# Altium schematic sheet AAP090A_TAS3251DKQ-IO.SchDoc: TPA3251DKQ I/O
size 538 x 342 mm; Date: Not shown in title block; ApprovedBy: Not shown in title block; CheckedBy: Not shown in title block; Author: Not shown in title block; CompanyName: Not shown in title block; DrawnBy: LDN; Engineer: Not shown in title block; Organization: Not shown in title block; Address1: Not shown in title block; Address2: Not shown in title block; Address3: Not shown in title block; Address4: Not shown in title block; DocumentNumber: 4; Revision: Use project parameter SCH_Rev; SheetNumber: 4; SheetTotal: 6; PageSetup: Record=PageOptions¦CenterHorizontal=True¦CenterVertical=True¦PrintScale=1.00¦XCorrection=1.00¦YCorrection=1.00¦PrintKind=0¦BorderSize=5000000¦LeftOffset=0¦BottomOffset=0¦Orientation=2¦PaperLength=1000¦PaperWidth=1000¦Scale=100¦PaperSource=15¦PrintQuality=600¦MediaType=1¦DitherType=10¦PaperKind=Letter¦PrintScaleMode=1
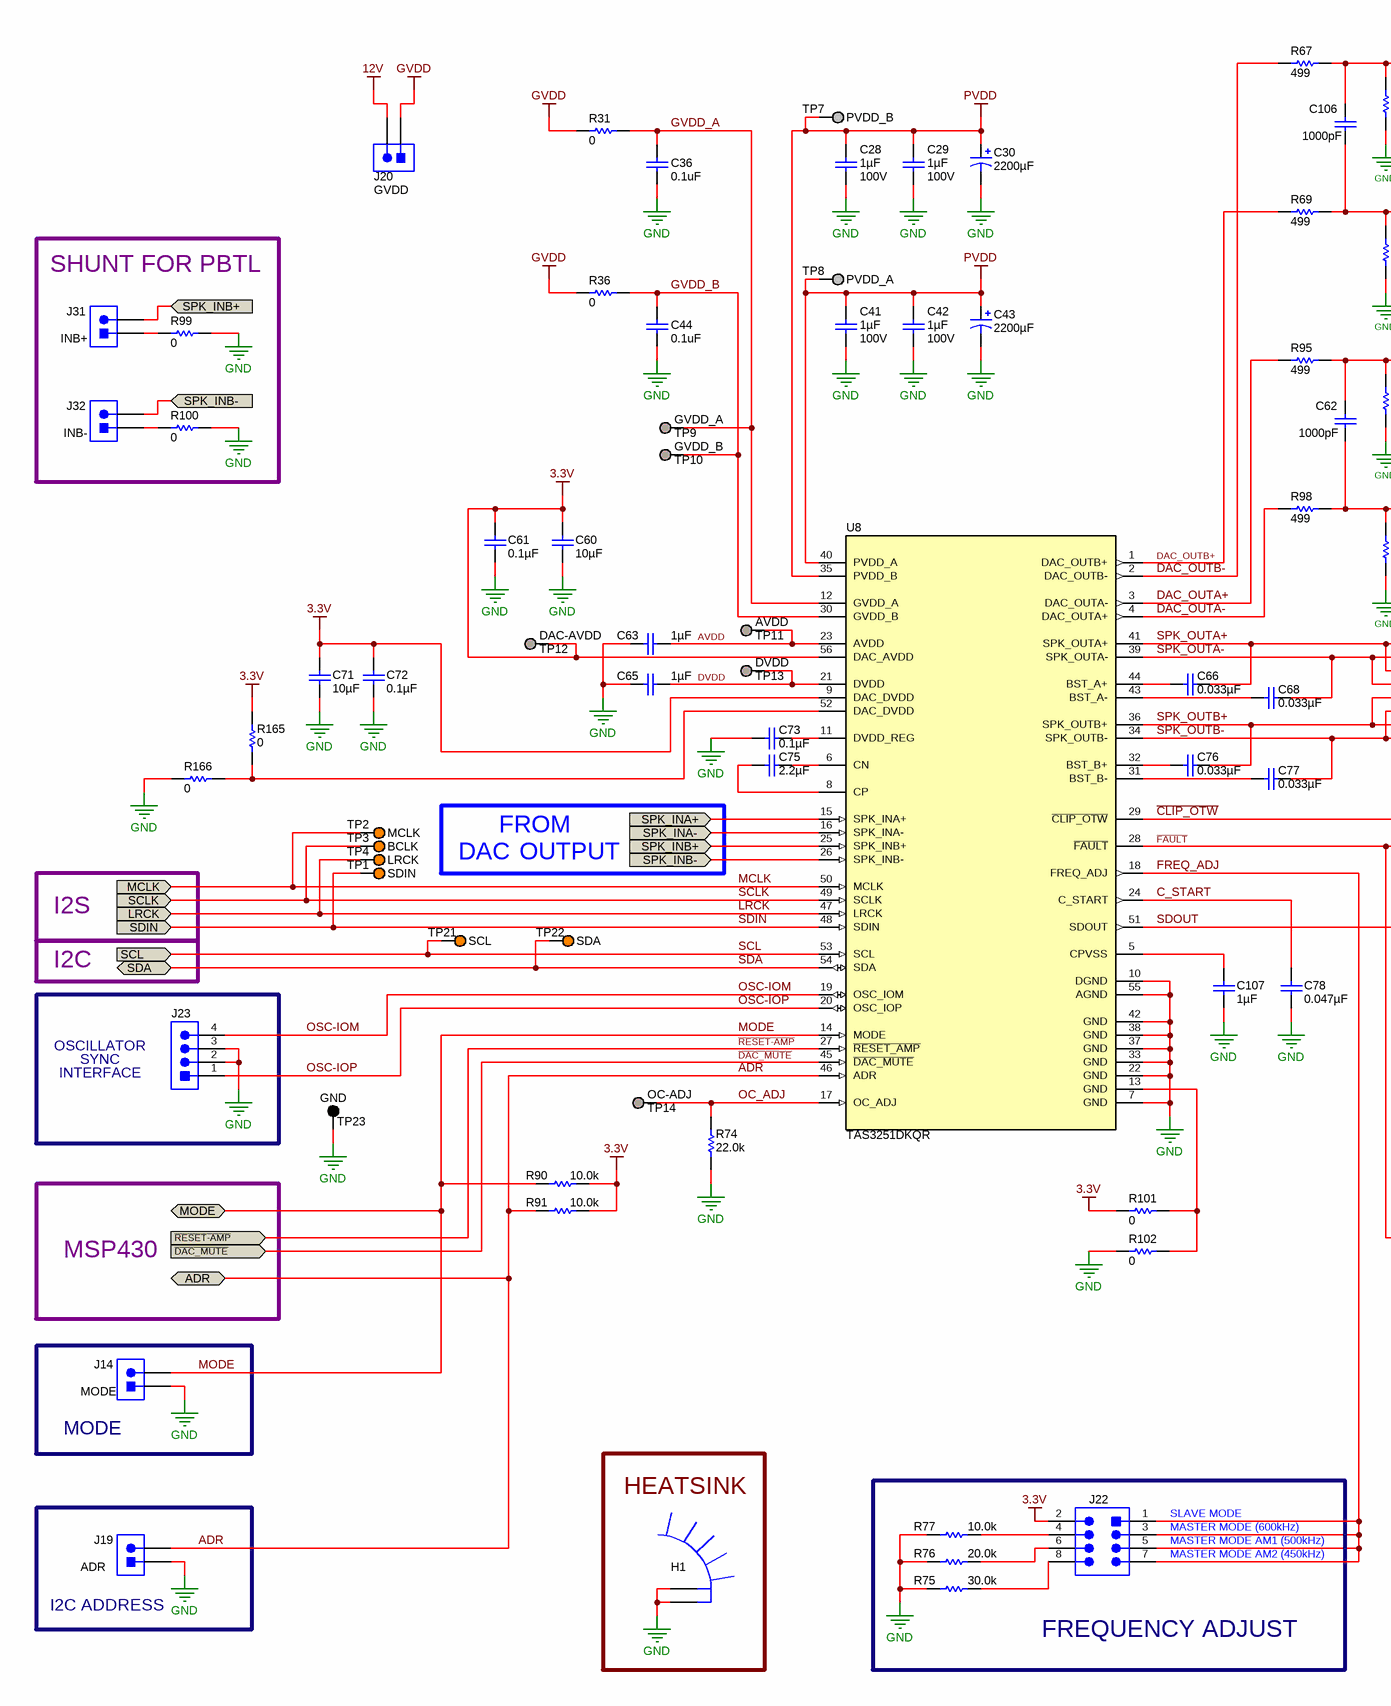
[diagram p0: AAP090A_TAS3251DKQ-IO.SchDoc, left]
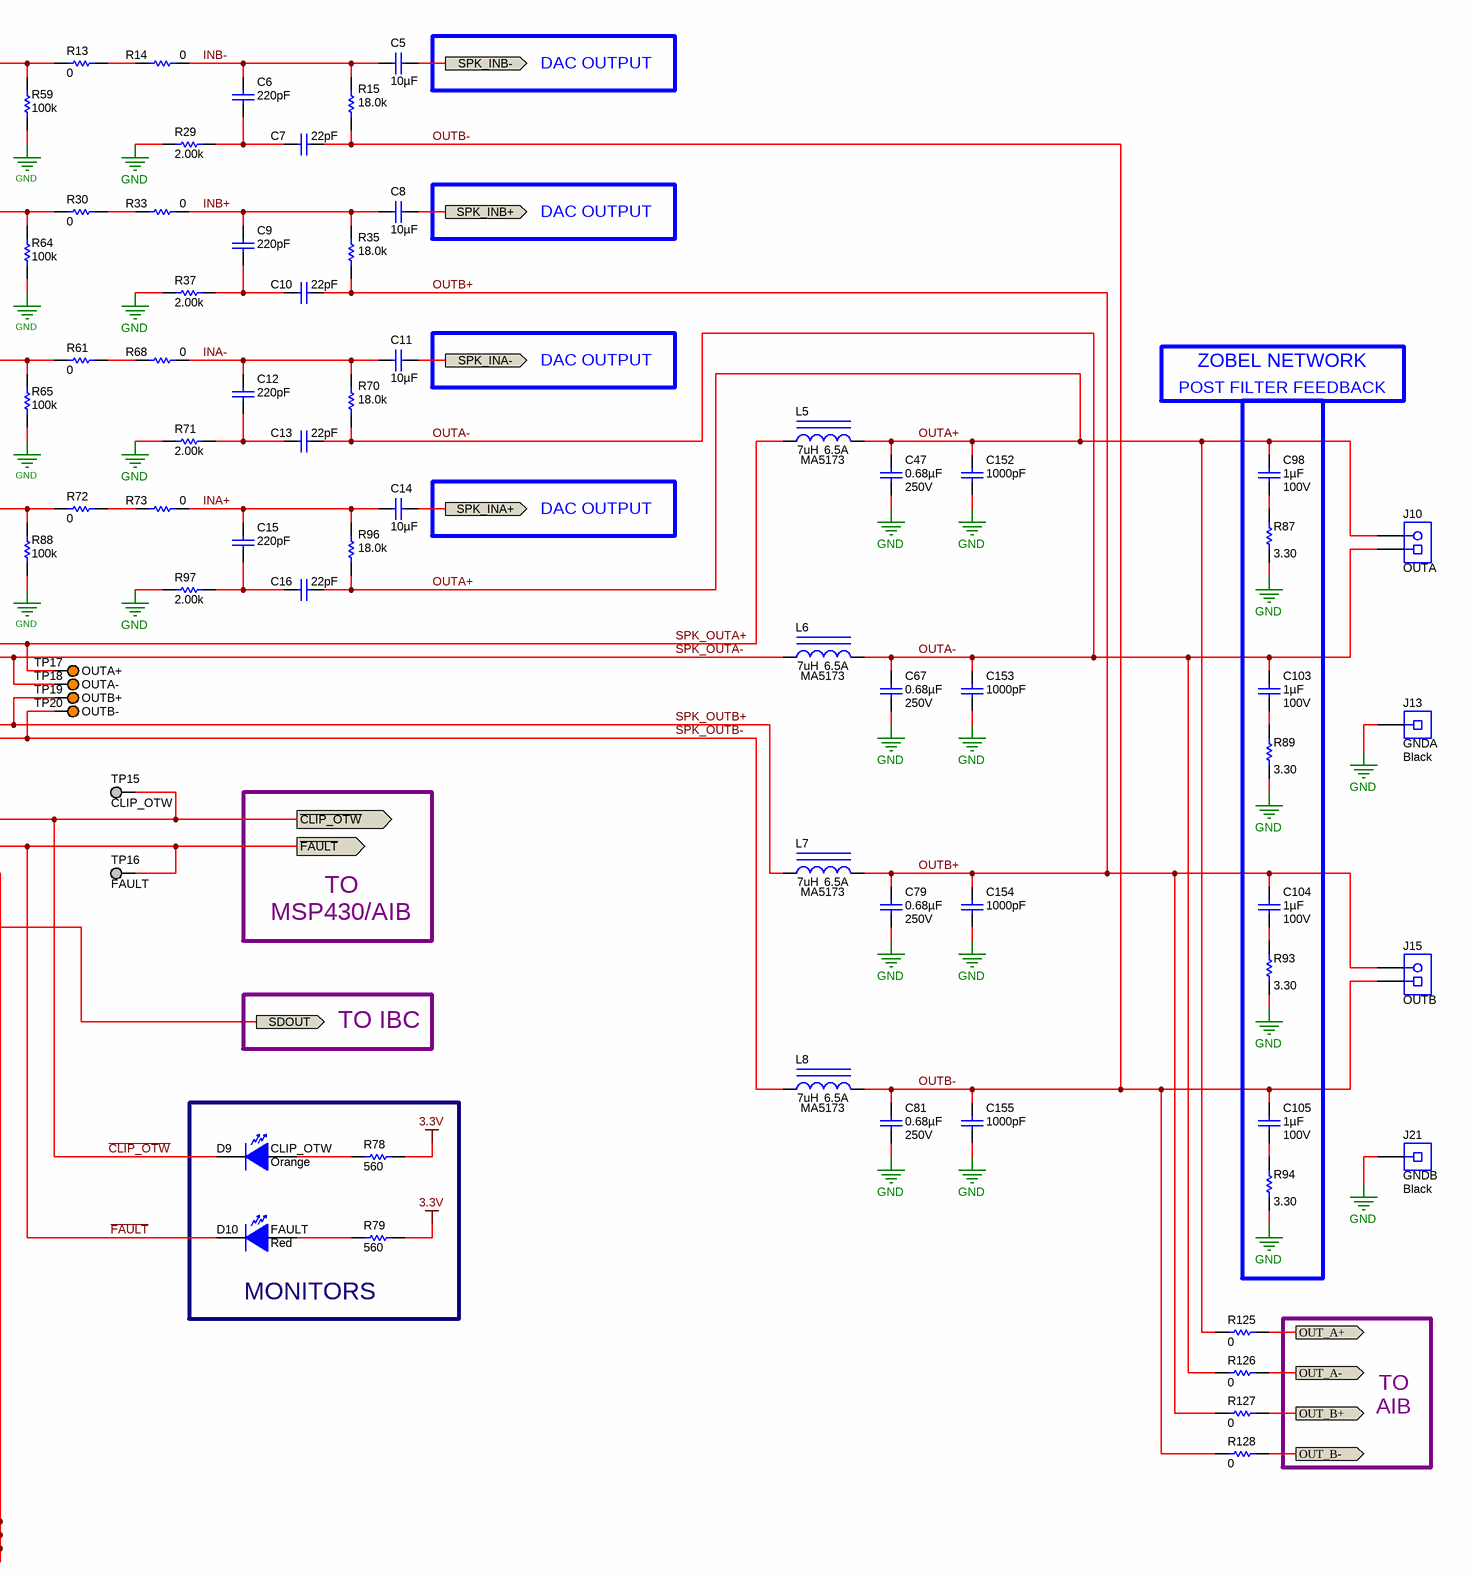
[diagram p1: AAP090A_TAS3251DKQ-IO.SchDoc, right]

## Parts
C5  ValueDisplayed: 10µF  [1206_180L]  (hidden comment: GRM31CR71C106KAC7L)
C6  ValueDisplayed: 220pF  [0603L]  (hidden comment: DNP)
C7  ValueDisplayed: 22pF  [0603L]  (hidden comment: DNP)
C8  ValueDisplayed: 10µF  [1206_180L]  (hidden comment: GRM31CR71C106KAC7L)
C9  ValueDisplayed: 220pF  [0603L]  (hidden comment: DNP)
C10  ValueDisplayed: 22pF  [0603L]  (hidden comment: DNP)
C11  ValueDisplayed: 10µF  [1206_180L]  (hidden comment: GRM31CR71C106KAC7L)
C12  ValueDisplayed: 220pF  [0603L]  (hidden comment: DNP)
C13  ValueDisplayed: 22pF  [0603L]  (hidden comment: DNP)
C14  ValueDisplayed: 10µF  [1206_180L]  (hidden comment: GRM31CR71C106KAC7L)
C15  ValueDisplayed: 220pF  [0603L]  (hidden comment: DNP)
C16  ValueDisplayed: 22pF  [0603L]  (hidden comment: DNP)
C28  ValueDisplayed: 1µF  Value2: 100V  [1206_180L]  (hidden comment: GRM31CR72A105KA01L)
C29  ValueDisplayed: 1µF  Value2: 100V  [1206_180L]  (hidden comment: GRM31CR72A105KA01L)
C30  ValueDisplayed: 2200µF  [FC_1800x3550]  (hidden comment: +)
C36  value 0.1uF  [0603L]  (hidden comment: C0603C104K5RACTU)
C41  ValueDisplayed: 1µF  Value2: 100V  [1206_180L]  (hidden comment: GRM31CR72A105KA01L)
C42  ValueDisplayed: 1µF  Value2: 100V  [1206_180L]  (hidden comment: GRM31CR72A105KA01L)
C43  ValueDisplayed: 2200µF  [FC_1800x3550]  (hidden comment: +)
C44  value 0.1uF  [0603L]  (hidden comment: C0603C104K5RACTU)
C47  ValueDisplayed: 0.68µF  Value2: 250V  [B32652_1800x900x1750]  (hidden comment: B32652A3684J)
C60  ValueDisplayed: 10µF  [0603L]  (hidden comment: GRM188R61A106ME69D)
C61  ValueDisplayed: 0.1µF  [0402L]  (hidden comment: GRM155R71A104KA01D)
C62  ValueDisplayed: 1000pF  [0402L]  (hidden comment: GRM1555C1H102JA01D)
C63  ValueDisplayed: 1µF  [0603L]  (hidden comment: GRM188R71C105KA12D)
C65  ValueDisplayed: 1µF  [0603L]  (hidden comment: GRM188R71C105KA12D)
C66  ValueDisplayed: 0.033µF  [0603L]  (hidden comment: GRM188R71E333KA01D)
C67  ValueDisplayed: 0.68µF  Value2: 250V  [B32652_1800x900x1750]  (hidden comment: B32652A3684J)
C68  ValueDisplayed: 0.033µF  [0603L]  (hidden comment: GRM188R71E333KA01D)
C71  ValueDisplayed: 10µF  [0603L]  (hidden comment: GRM188R61A106ME69D)
C72  ValueDisplayed: 0.1µF  [0402L]  (hidden comment: GRM155R71A104KA01D)
C73  ValueDisplayed: 0.1µF  [0402L]  (hidden comment: GRM155R71A104KA01D)
C75  ValueDisplayed: 2.2µF  [0402L]  (hidden comment: C1005X5R1A225K050BC)
C76  ValueDisplayed: 0.033µF  [0603L]  (hidden comment: GRM188R71E333KA01D)
C77  ValueDisplayed: 0.033µF  [0603L]  (hidden comment: GRM188R71E333KA01D)
C78  ValueDisplayed: 0.047µF  [0603L]  (hidden comment: GRM188R71H473KA61D)
C79  ValueDisplayed: 0.68µF  Value2: 250V  [B32652_1800x900x1750]  (hidden comment: B32652A3684J)
C81  ValueDisplayed: 0.68µF  Value2: 250V  [B32652_1800x900x1750]  (hidden comment: B32652A3684J)
C98  ValueDisplayed: 1µF  Value2: 100V  [1206_180L]  (hidden comment: DNP)
C103  ValueDisplayed: 1µF  Value2: 100V  [1206_180L]  (hidden comment: DNP)
C104  ValueDisplayed: 1µF  Value2: 100V  [1206_180L]  (hidden comment: DNP)
C105  ValueDisplayed: 1µF  Value2: 100V  [1206_180L]  (hidden comment: DNP)
C106  ValueDisplayed: 1000pF  [0402L]  (hidden comment: GRM1555C1H102JA01D)
C107  ValueDisplayed: 1µF  [0603L]  (hidden comment: GRM188R71C105KA12D)
C152  ValueDisplayed: 1000pF  [1206L]  (hidden comment: DNP)
C153  ValueDisplayed: 1000pF  [1206L]  (hidden comment: DNP)
C154  ValueDisplayed: 1000pF  [1206L]  (hidden comment: DNP)
C155  ValueDisplayed: 1000pF  [1206L]  (hidden comment: DNP)
D9  CLIP_OTW  value Orange  [LTST-C170KFKT_Orange]
D10  FAULT  value Red  [LED_LTST-C170_Red]
H1  ATS078036036-TI1OP-1099-C1-R1  [Advanced_ATS078036036-TI1OP-1099-C1-R1]  (value not drawn)
J10  OUTA  [Pomona_6883]
J13  GNDA  Shell Color: Black  [Keystone_7007]
J14  MODE  [Sullins_PBC02SAAN]
J15  OUTB  [Pomona_6883]
J19  ADR  [Sullins_PBC02SAAN]
J20  GVDD  [Sullins_PBC02SAAN]
J21  GNDB  Shell Color: Black  [Keystone_7007]
J22  PEC04DAAN  [CONN_PEC04DAAN]  (value not drawn)
J23  0022112042  [CONN_22112042]  (value not drawn)
J31  INB+  [Sullins_PBC02SAAN]
J32  INB-  [Sullins_PBC02SAAN]
L5  MA5173  value 7uH  Value2: 6.5A  [MA5173]
L6  MA5173  value 7uH  Value2: 6.5A  [MA5173]
L7  MA5173  value 7uH  Value2: 6.5A  [MA5173]
L8  MA5173  value 7uH  Value2: 6.5A  [MA5173]
R13  ValueDisplayed: 0  [1206L]  (hidden comment: RC1206JR-070RL)
R14  ValueDisplayed: 0  [0805_KTR]
R15  ValueDisplayed: 18.0k  [0603L]  (hidden comment: DNP)
R29  ValueDisplayed: 2.00k  [0603L]  (hidden comment: DNP)
R30  ValueDisplayed: 0  [1206L]  (hidden comment: RC1206JR-070RL)
R31  ValueDisplayed: 0  [0805_KTR]  (hidden comment: RC0805JR-070RL)
R33  ValueDisplayed: 0  [0805_KTR]
R35  ValueDisplayed: 18.0k  [0603L]  (hidden comment: DNP)
R36  ValueDisplayed: 0  [0805_KTR]  (hidden comment: RC0805JR-070RL)
R37  ValueDisplayed: 2.00k  [0603L]  (hidden comment: DNP)
R59  ValueDisplayed: 100k  [0603L]  (hidden comment: RC0603FR-07100KL)
R61  ValueDisplayed: 0  [1206L]  (hidden comment: RC1206JR-070RL)
R64  ValueDisplayed: 100k  [0603L]  (hidden comment: RC0603FR-07100KL)
R65  ValueDisplayed: 100k  [0603L]  (hidden comment: RC0603FR-07100KL)
R67  ValueDisplayed: 499  [0603L]  (hidden comment: RC0603FR-07499RL)
R68  ValueDisplayed: 0  [0805_KTR]
R69  ValueDisplayed: 499  [0603L]  (hidden comment: RC0603FR-07499RL)
R70  ValueDisplayed: 18.0k  [0603L]  (hidden comment: DNP)
R71  ValueDisplayed: 2.00k  [0603L]  (hidden comment: DNP)
R72  ValueDisplayed: 0  [1206L]  (hidden comment: RC1206JR-070RL)
R73  ValueDisplayed: 0  [0805_KTR]
R74  ValueDisplayed: 22.0k  [0603L]  (hidden comment: RC0603FR-0722KL)
R75  ValueDisplayed: 30.0k  [0603L]  (hidden comment: RC0603FR-0730KL)
R76  ValueDisplayed: 20.0k  [0603L]  (hidden comment: RC0603FR-0720KL)
R77  ValueDisplayed: 10.0k  [0201L]  (hidden comment: RC0201FR-0710KL)
R78  ValueDisplayed: 560  [0603L]  (hidden comment: RC0603JR-07560RL)
R79  ValueDisplayed: 560  [0603L]  (hidden comment: RC0603JR-07560RL)
R87  ValueDisplayed: 3.30  [1206L]  (hidden comment: DNP)
R88  ValueDisplayed: 100k  [0603L]  (hidden comment: RC0603FR-07100KL)
R89  ValueDisplayed: 3.30  [1206L]  (hidden comment: DNP)
R90  ValueDisplayed: 10.0k  [0201L]  (hidden comment: RC0201FR-0710KL)
R91  ValueDisplayed: 10.0k  [0201L]  (hidden comment: RC0201FR-0710KL)
R93  ValueDisplayed: 3.30  [1206L]  (hidden comment: DNP)
R94  ValueDisplayed: 3.30  [1206L]  (hidden comment: DNP)
R95  ValueDisplayed: 499  [0603L]  (hidden comment: RC0603FR-07499RL)
R96  ValueDisplayed: 18.0k  [0603L]  (hidden comment: DNP)
R97  ValueDisplayed: 2.00k  [0603L]  (hidden comment: DNP)
R98  ValueDisplayed: 499  [0603L]  (hidden comment: RC0603FR-07499RL)
R99  ValueDisplayed: 0  [0603L]  (hidden comment: ERJ-3GEY0R00V)
R100  ValueDisplayed: 0  [0603L]  (hidden comment: ERJ-3GEY0R00V)
R101  ValueDisplayed: 0  [0603L]  (hidden comment: DNP)
R102  ValueDisplayed: 0  [0603L]  (hidden comment: ERJ-3GEY0R00V)
R125  ValueDisplayed: 0  [0805_KTR]  (hidden comment: RC0805JR-070RL)
R126  ValueDisplayed: 0  [0805_KTR]  (hidden comment: RC0805JR-070RL)
R127  ValueDisplayed: 0  [0805_KTR]  (hidden comment: RC0805JR-070RL)
R128  ValueDisplayed: 0  [0805_KTR]  (hidden comment: RC0805JR-070RL)
R165  ValueDisplayed: 0  [0603L]  (hidden comment: ERJ-3GEY0R00V)
R166  ValueDisplayed: 0  [0603L]  (hidden comment: DNP)
TP1  SDIN  [Keystone5003]
TP2  MCLK  [Keystone5003]
TP3  BCLK  [Keystone5003]
TP4  LRCK  [Keystone5003]
TP7  PVDD_B  [Keystone5128]
TP8  PVDD_A  [Keystone5128]
TP9  GVDD_A  [TP_H045P075]  (no BOM)
TP10  GVDD_B  [TP_H045P075]  (no BOM)
TP11  AVDD  [TP_H045P075]  (no BOM)
TP12  DAC-AVDD  [TP_H045P075]  (no BOM)
TP13  DVDD  [TP_H045P075]  (no BOM)
TP14  OC-ADJ  [TP_H045P075]  (no BOM)
TP15  CLIP_OTW  [Keystone5128]
TP16  FAULT  [Keystone5128]
TP17  OUTA+  [Keystone5003]
TP18  OUTA-  [Keystone5003]
TP19  OUTB+  [Keystone5003]
TP20  OUTB-  [Keystone5003]
TP21  SCL  [Keystone5003]
TP22  SDA  [Keystone5003]
TP23  GND  [Keystone5001]
U8  TAS3251DKQR  [DKQ0056A]

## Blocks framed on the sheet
SHUNT FOR PBTL: J31 J32 R99 R100
POST FILTER FEEDBACK: C98 C103-C105 R87 R89 R93 R94
MONITORS: D9 D10 R78 R79
MODE: J14
I2C ADDRESS: J19
HEATSINK: H1
FREQUENCY ADJUST: J22 R75-R77

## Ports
ADR (bidir), LRCK (in), MCLK (in), MODE (bidir), OUT_A+ (out), OUT_A- (out), OUT_B+ (out), OUT_B- (out), SCL (in), SCLK (in), SDA (bidir), SDIN (in), SDOUT (out), SPK_INA+ (in), SPK_INA+ (out), SPK_INA- (in), SPK_INA- (out), SPK_INB+ (in), SPK_INB+ (out), SPK_INB- (in), SPK_INB- (out), ~{CLIP_OTW} (out), ~{DAC_MUTE} (in), ~{FAULT} (out), ~{RESET-AMP} (in)

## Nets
3.3V: C60.1 C61.1 C71.1 C72.1 J22.2 R78.2 R79.2 R90.1 R91.1 R101.1 R165.2 TP12.1 U8.9(DAC_DVDD) U8.56(DAC_AVDD)
12V: J20.2
GND: C28.1 C29.1 C30.2(-) C36.2 C41.1 C42.1 C43.2(-) C44.2 C47.2 C60.2 C61.2 C63.1 C65.1 C67.2 C71.2 C72.2 C73.2 C78.2 C79.2 C81.2 C107.1 C152.1 C153.1 C154.1 C155.1 H1.1 H1.2 J13.1 J14.1 J19.1 J21.1 J23.2 J23.3 R29.1 R37.1 R59.1 R64.1 R65.1 R71.1 R74.1 R75.1 R76.1 R77.1 R87.1 R88.1 R89.1 R93.1 R94.1 R97.1 R99.1 R100.1 R102.1 R166.1 TP23.1 U8.7(GND) U8.10(DGND) U8.22(GND) U8.33(GND) U8.37(GND) U8.38(GND) U8.42(GND) U8.55(AGND)
GVDD: J20.1 R31.1 R36.1
PVDD: C28.2 C29.2 C30.1(+) C41.2 C42.2 C43.1(+) TP7.1 TP8.1 U8.35(PVDD_B) U8.40(PVDD_A)
~{CLIP_OTW}: D9.2(K) TP15.1 U8.29(~{CLIP_OTW}) ; port ~{CLIP_OTW}
~{DAC_MUTE}: U8.45(~{DAC_MUTE}) ; port ~{DAC_MUTE}
~{FAULT}: D10.2(K) TP16.1 U8.28(~{FAULT}) ; port ~{FAULT}
~{RESET-AMP}: U8.27(~{RESET_AMP}) ; port ~{RESET-AMP}
ADR: J19.2 R91.2 U8.46(ADR) ; port ADR
AVDD: C63.2 TP11.1 U8.23(AVDD)
C_START: C78.1 U8.24(C_START)
DAC_OUTA+: R95.1 U8.3(DAC_OUTA-)
DAC_OUTA-: R98.1 U8.4(DAC_OUTA+)
DAC_OUTB+: R69.1 U8.1(DAC_OUTB+)
DAC_OUTB-: R67.1 U8.2(DAC_OUTB-)
DVDD: C65.2 TP13.1 U8.21(DVDD)
FREQ_ADJ: J22.1 J22.3 J22.5 J22.7 U8.18(FREQ_ADJ)
GVDD_A: C36.1 R31.2 TP9.1 U8.12(GVDD_A)
GVDD_B: C44.1 R36.2 TP10.1 U8.30(GVDD_B)
INA+: C14.1 C15.1 R73.2 R96.2
INA-: C11.1 C12.1 R68.2 R70.2
INB+: C8.1 C9.1 R33.2 R35.2
INB-: C5.1 C6.1 R14.2 R15.2
LRCK: TP4.1 U8.47(LRCK) ; port LRCK
MCLK: TP2.1 U8.50(MCLK) ; port MCLK
MODE: J14.2 R90.2 U8.14(MODE) ; port MODE
OC_ADJ: R74.2 TP14.1 U8.17(OC_ADJ)
OSC-IOM: J23.4 U8.19(OSC_IOM)
OSC-IOP: J23.1 U8.20(OSC_IOP)
OUT_A+: R125.2 ; port OUT_A+
OUT_A-: R126.2 ; port OUT_A-
OUT_B+: R127.2 ; port OUT_B+
OUT_B-: R128.2 ; port OUT_B-
OUTA+: C16.1 C47.1 C98.2 C152.2 J10.2 L5.2 R96.1 R125.1
OUTA-: C13.1 C67.1 C103.2 C153.2 J10.1 L6.2 R70.1 R126.1
OUTB+: C10.1 C79.1 C104.2 C154.2 J15.2 L7.2 R35.1 R127.1
OUTB-: C7.1 C81.1 C105.2 C155.2 J15.1 L8.2 R15.1 R128.1
SCL: TP21.1 U8.53(SCL) ; port SCL
SCLK: TP3.1 U8.49(SCLK) ; port SCLK
SDA: TP22.1 U8.54(SDA) ; port SDA
SDIN: TP1.1 U8.48(SDIN) ; port SDIN
SDOUT: U8.51(SDOUT) ; port SDOUT
SPK_INA+: C14.2 U8.15(SPK_INA+) ; port SPK_INA+
SPK_INA-: C11.2 U8.16(SPK_INA-) ; port SPK_INA-
SPK_INB+: C8.2 J31.2 U8.25(SPK_INB+) ; port SPK_INB+
SPK_INB-: C5.2 J32.2 U8.26(SPK_INB-) ; port SPK_INB-
SPK_OUTA+: C66.1 L5.1 TP17.1 U8.41(SPK_OUTA+)
SPK_OUTA-: C68.1 L6.1 TP18.1 U8.39(SPK_OUTA-)
SPK_OUTB+: C76.1 L7.1 TP19.1 U8.36(SPK_OUTB+)
SPK_OUTB-: C77.1 L8.1 TP20.1 U8.34(SPK_OUTB-)
NetC6_2: C6.2 C7.2 R29.2
NetC9_2: C9.2 C10.2 R37.2
NetC12_2: C12.2 C13.2 R71.2
NetC15_2: C15.2 C16.2 R97.2
NetC62_1: C62.1 R61.1 R65.2 R95.2
NetC62_2: C62.2 R72.1 R88.2 R98.2
NetC66_2: C66.2 U8.44(BST_A+)
NetC68_2: C68.2 U8.43(BST_A-)
NetC73_1: C73.1 U8.11(DVDD_REG)
NetC75_1: C75.1 U8.6(CN)
NetC75_2: C75.2 U8.8(CP)
NetC76_2: C76.2 U8.32(BST_B+)
NetC77_2: C77.2 U8.31(BST_B-)
NetC98_1: C98.1 R87.2
NetC103_1: C103.1 R89.2
NetC104_1: C104.1 R93.2
NetC105_1: C105.1 R94.2
NetC106_1: C106.1 R13.1 R59.2 R67.2
NetC106_2: C106.2 R30.1 R64.2 R69.2
NetC107_2: C107.2 U8.5(CPVSS)
NetD9_1: D9.1(A) R78.1
NetD10_1: D10.1(A) R79.1
NetJ22_4: J22.4 R77.2
NetJ22_6: J22.6 R76.2
NetJ22_8: J22.8 R75.2
NetJ31_1: J31.1 R99.2
NetJ32_1: J32.1 R100.2
NetR13_2: R13.2 R14.1
NetR30_2: R30.2 R33.1
NetR61_2: R61.2 R68.1
NetR72_2: R72.2 R73.1
NetR101_2: R101.2 R102.2 U8.13(GND)
NetR165_1: R165.1 R166.2 U8.52(DAC_DVDD)

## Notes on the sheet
- DAC OUTPUT
- ZOBEL NETWORK
- DAC
- FROM
- OUTPUT
- I2S
- MSP430/AIB
- TO
- I2C
- OSCILLATOR
- SYNC
- INTERFACE
- TO IBC
- MSP430
- AIB
- (near J22) SLAVE MODE
- (near J22) MASTER MODE (600kHz)
- (near J22) MASTER MODE AM1 (500kHz)
- (near J22) MASTER MODE AM2 (450kHz)

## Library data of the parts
C5 C8 C11 C14 = GRM31CR71C106KAC7L: CAP, CERM, 10 µF, 16 V, +/- 10%, X7R, 1206; Manufacturer: MuRata; Polarized: N; CompType: Capacitor; Value: 10uF; U/M: EA; Cap_F: 0.00001; Tolerance_%: 10; Value1: Unknown; VDC_V: 16; Value2: 16V; TaMin_C: -55; TaMax_C: 125; Cap_Case: 1206; AEC Category: Q200; SizeArea_mm2: 5.12; SizeAreaWB_mm2: 10.92; SizeX_mm: 3.2; SizeY_mm: 1.6; SizeZ_mm: 1.8
C6 C9 C12 C15 = GRM1885C1H221JA01D: CAP, CERM, 220 pF, 50 V,+/- 5%, C0G/NP0, 0603; Manufacturer: MuRata; Polarized: N; CompType: Capacitor; Value: 220pF; U/M: EA; Cap_F: 0.00000000022; Tolerance_%: 5; VDC_V: 50; Value2: 50V; TaMin_C: -55; TaMax_C: 125; Cap_Case: 0603; AEC Category: Q200; SizeArea_mm2: 1.28; SizeAreaWB_mm2: 4.68; SizeX_mm: 1.6; SizeY_mm: 0.8; SizeZ_mm: 1; Green_Lifecycle: Active; Green_REACh: Passed
C7 C10 C13 C16 = GRM1885C1H220JA01D: CAP, CERM, 22 pF, 50 V, +/- 5%, C0G/NP0, 0603; Manufacturer: MuRata; Polarized: N; CompType: Capacitor; Value: 22pF; U/M: EA; Cap_F: 0.000000000022; Tolerance_%: 5; Value1: Unknown; VDC_V: 50; Value2: 50V; TaMin_C: -55; TaMax_C: 125; Cap_Case: 0603; AEC Category: Q200
C28 C29 C41 C42 C98 C103-C105 = GRM31CR72A105KA01L: CAP, CERM, 1 µF, 100 V, +/- 10%, X7R, 1206; Manufacturer: MuRata; Polarized: N; CompType: Capacitor; Value: 1uF; U/M: EA; Cap_F: 0.000001; Tolerance_%: 10; Value1: Unknown; VDC_V: 100; TaMin_C: -55; TaMax_C: 125; Cap_Case: 2220; SizeArea_mm2: 5.12; SizeAreaWB_mm2: 10.92; SizeX_mm: 3.2; SizeY_mm: 1.6; SizeZ_mm: 1.8; AEC Category: Q200
C30 C43 = EEU-FC1H222: CAP, AL, 2200 µF, 50 V, +/- 20%, 0.023 ohm, TH; Manufacturer: Panasonic; Polarized: Y; CompType: Capacitor; Value: 2200uF; U/M: EA; Cap_F: 0.0022; Tolerance_%: 20; VDC_V: 50; Value2: 50V; ESR_ohm: 0.023; IRMS_A: 3.1; TaMin_C: -55; TaMax_C: 105; Cap_Case: 18x35.5mm
C36 C44 = C0603C104K5RACTU: CAP, CERM, 0.1 µF, 50 V, +/- 10%, X7R, 0603; Manufacturer: Kemet; Polarized: N; CompType: Capacitor; ValueDisplayed: 0.1µF; U/M: EA; Cap_F: 0.0000001; Tolerance_%: 10; Value1: Unknown; VDC_V: 50; Value2: 50V; TaMin_C: -55; TaMax_C: 125; Cap_Case: 0603; AEC Category: Q200
C47 C67 C79 C81 = B32652A3684J: CAP, Film, 0.68 µF, 250 V, +/- 5%, TH; Manufacturer: EPCOS Inc; Polarized: N; CompType: Capacitor; Value: 0.68uF; U/M: EA; Cap_F: 0.00000068; Tolerance_%: 5; Value1: Unknown; VDC_V: 250; TaMin_C: -55; TaMax_C: 110; Cap_Case: 18x9x17.5mm
C60 C71 = GRM188R61A106ME69D: CAP, CERM, 10 µF, 10 V, +/- 20%, X5R, 0603; Manufacturer: MuRata; Polarized: N; CompType: Capacitor; Value: 10uF; U/M: EA; Cap_F: 0.00001; Tolerance_%: 20; Value1: Unknown; VDC_V: 10; Value2: 10V; TaMin_C: -55; TaMax_C: 85; Cap_Case: 0603; AEC Category: Q200
C61 C72 C73 = GRM155R71A104KA01D: CAP, CERM, 0.1 µF, 10 V, +/- 10%, X7R, 0402; Manufacturer: MuRata; Polarized: N; CompType: Capacitor; Value: 0.1uF; U/M: EA; Cap_F: 0.0000001; Tolerance_%: 10; Value1: Unknown; Value2: 10V; TaMin_C: -55; TaMax_C: 125; Cap_Case: 0402; AEC Category: Q200
C62 C106 = GRM1555C1H102JA01D: CAP, CERM, 1000 pF, 50 V, +/- 5%, C0G/NP0, 0402; Manufacturer: MuRata; Polarized: N; CompType: Capacitor; Value: 1000pF; U/M: EA; Cap_F: 0.000000001; Tolerance_%: 5; Value1: Unknown; VDC_V: 50; Value2: 50V; TaMin_C: -55; TaMax_C: 125; Cap_Case: 0402; AEC Category: Q200
C63 C65 C107 = GRM188R71C105KA12D: CAP, CERM, 1 µF, 16 V, +/- 10%, X7R, 0603; Manufacturer: MuRata; Polarized: N; CompType: Capacitor; Value: 1uF; U/M: EA; Cap_F: 0.000001; Tolerance_%: 10; ESR_ohm: 0.011; Value1: 0.011 ohm; VDC_V: 16; Value2: 16V; TaMin_C: -55; TaMax_C: 125; Cap_Case: 0603; AEC Category: Q200
C66 C68 C76 C77 = GRM188R71E333KA01D: CAP, CERM, 0.033 µF, 25 V, +/- 10%, X7R, 0603; Manufacturer: MuRata; Polarized: N; CompType: Capacitor; Value: 0.033uF; U/M: EA; Cap_F: 0.000000033; Tolerance_%: 10; Value1: Unknown; VDC_V: 25; Value2: 25V; TaMin_C: -55; TaMax_C: 125; Cap_Case: 0603; AEC Category: Q200
C75 = C1005X5R1A225K050BC: CAP, CERM, 2.2 µF, 10 V, +/- 10%, X5R, 0402; Manufacturer: TDK; Polarized: N; CompType: Capacitor; Value: 2.2uF; U/M: EA; Cap_F: 0.0000022; Tolerance_%: 10; Value1: Unknown; Value2: 10V; TaMin_C: -55; TaMax_C: 85; Cap_Case: 0402; AEC Category: Q200
C78 = GRM188R71H473KA61D: CAP, CERM, 0.047 µF, 50 V, +/- 10%, X7R, 0603; Manufacturer: MuRata; Polarized: N; CompType: Capacitor; Value: 0.047uF; U/M: EA; Cap_F: 0.000000047; Tolerance_%: 10; Value1: Unknown; VDC_V: 50; Value2: 50V; TaMin_C: -55; TaMax_C: 125; Cap_Case: 0603; AEC Category: Q200
C152-C155 = GRM3195C1H102JA01D: CAP, CERM, 1000 pF, 50 V, +/- 5%, C0G/NP0, 1206; Manufacturer: MuRata; Polarized: N; CompType: Capacitor; Value: 1000pF; U/M: EA; Cap_F: 0.000000001; Tolerance_%: 5; Value1: Unknown; VDC_V: 50; Value2: 50V; TaMin_C: -55; TaMax_C: 125; Cap_Case: 1206
D9 = LTST-C170KFKT: LED, Orange, SMD; Manufacturer: Lite-On; Type: AlInGaP; Vf_V: 2; Value2: 2V; Io_A: 0.02; Value1: W; U/M: EA
D10 = LTST-C170KRKT: LED, Red, SMD; Manufacturer: Lite-On; Type: AlInGaP; Vf_V: 2; Value2: 2V; Io_A: 0.02; Value1: W; SizeAreaWB_mm2: 6.75; SizeArea_mm2: 2.5; SizeY_mm: 1.25; SizeZ_mm: 1.2; U/M: EA
H1 = CMP-0078258-2: Heat Sink, 36x78x36.5mm; Manufacturer: Advanced Thermal Solutions
J10 J15 = CMP-0075104-1: Dual Binding Posts with Base, 2x1, TH; Manufacturer: Pomona Electronics; PartNumber: 6883; CNHeader: False; Green_Lifecycle: Not Set; Green_REACh: Incomplete; CompType: Connector
J13 J21 = 7007: Binding Post, BLACK, TH; Manufacturer: Keystone; SymbolCreator: a0799628; CompType: Connector; U/M: EA
J14 J19 J20 J31 J32 = PBC02SAAN: Header, 100mil, 2x1, Gold, TH; Manufacturer: Sullins Connector Solutions; SymbolCreator: a0412235; Pitch_mm: 2.54; Gender: Male; Shrouded: N; Row_Count: 1; Current_A: 3; Voltage_V: 1800; Cert_UL: Y
J22 = PEC04DAAN: Header, 100mil, 4x2, Tin, TH; Manufacturer: Sullins Connector Solutions; SymbolCreator: a0411947; Pitch_mm: 2.54; Gender: Male; Shrouded: N; Row_Count: 2; Current_A: 3; Voltage_V: 1800; Cert_UL: Y
J23 = 0022112042: Header (friction lock), 100mil, 4x1, Gold, TH; Manufacturer: Molex; SymbolCreator: a0412235
L5-L8 = MA5173-AE: Inductor, Toroid, Powdered Iron, 7 µH, 6.5 A, 0.0215 ohm, TH; Manufacturer: Coilcraft; Ind_H: 7.0E-6; ValueDisplayed: 7µH; Imax_A: 6.5; Irms: 6.5A @ 20C rise; Isat: 54A @ 10% inductance drop; DCR_ohm: 0.0215
R13 R30 R61 R72 = RC1206JR-070RL: RES, 0, 5%, 0.25 W, 1206; Manufacturer: Yageo America; CompType: Resistor; Value: 0; Value_Code: 0000; Tolerance_%: 5; Power_W: 0.25; Value2: 0.25W; VDC_V: 200; TempCo: 200 ppm/C; EIA_Code: E24; U/M: EA; AEC Category: Q200; SizeArea_mm2: 5.12; SizeX_mm: 3.2; SizeY_mm: 1.6; SizeZ_mm: 1.35; Green_Lifecycle: Active; Green_REACh: Passed
R14 R33 R68 R73 = ERJ-6GEY0R00V: RES, 0, 5%, 0.125 W, 0805; Manufacturer: Panasonic; CompType: Resistor; Value: 0; Value_Code: 0000; Tolerance_%: 5; Power_W: 0.125; Value2: 0.125W; VDC_V: 150; TempCo: 600 ppm/C; EIA_Code: E24; U/M: EA; AEC Category: Q200
R15 R35 R70 R96 = RC0603FR-0718KL: RES, 18.0 k, 1%, 0.1 W, 0603; Manufacturer: Yageo America; CompType: Resistor; Value: 18.0k; Res_ohm: 18000; Value_Code: 18k0; Tolerance_%: 1; Power_W: 0.1; Value2: 0.1W; VDC_V: 150; TempCo: 200 ppm/C; U/M: EA; AEC Category: Q200
R29 R37 R71 R97 = RC0603FR-072KL: RES, 2.00 k, 1%, 0.1 W, 0603; Manufacturer: Yageo America; CompType: Resistor; Value: 2.00k; Res_ohm: 2000; Value_Code: 2k00; Tolerance_%: 1; Power_W: 0.1; Value2: 0.1W; VDC_V: 150; TempCo: 200 ppm/C; EIA_Code: E96; U/M: EA; AEC Category: Q200; SizeArea_mm2: 1.28; SizeX_mm: 1.6; SizeY_mm: 0.8; Green_Lifecycle: Active; Green_REACh: Passed
R31 R36 R125-R128 = RC0805JR-070RL: RES, 0, 5%, 0.125 W, 0805; Manufacturer: Yageo America; CompType: Resistor; Value: 0; Value_Code: 0000; Tolerance_%: 5; Power_W: 0.125; Value2: 0.125W; VDC_V: 150; TempCo: 200 ppm/C; EIA_Code: E24; U/M: EA; AEC Category: Q200; SizeArea_mm2: 2.5; SizeX_mm: 2; SizeY_mm: 1.25; SizeZ_mm: 1.45; Green_Lifecycle: Active; Green_REACh: Passed
R59 R64 R65 R88 = RC0603FR-07100KL: RES, 100 k, 1%, 0.1 W, 0603; Manufacturer: Yageo America; CompType: Resistor; Value: 100k; Res_ohm: 100000; Tolerance_%: 1; Power_W: 0.1; Value2: 0.1W; VDC_V: 150; TempCo: 200 ppm/C; EIA_Code: E96; U/M: EA; AEC Category: Q200; SizeArea_mm2: 1.28; SizeX_mm: 1.6; SizeY_mm: 0.8; Green_Lifecycle: Active; Green_REACh: Passed
R67 R69 R95 R98 = RC0603FR-07499RL: RES, 499, 1%, 0.1 W, 0603; Manufacturer: Yageo America; CompType: Resistor; Value: 499; Value_Code: 499R; Tolerance_%: 1; Power_W: 0.1; Value2: 0.1W; VDC_V: 150; TempCo: 200 ppm/C; EIA_Code: E96; U/M: EA; AEC Category: Q200; SizeArea_mm2: 1.28; SizeX_mm: 1.6; SizeY_mm: 0.8; Green_Lifecycle: Active; Green_REACh: Passed
R74 = RC0603FR-0722KL: RES, 22.0 k, 1%, 0.1 W, 0603; Manufacturer: Yageo America; CompType: Resistor; Value: 22.0k; Res_ohm: 22000; Value_Code: 22k0; Tolerance_%: 1; Power_W: 0.1; Value2: 0.1W; VDC_V: 150; TempCo: 200 ppm/C; U/M: EA; AEC Category: Q200
R75 = RC0603FR-0730KL: RES, 30.0 k, 1%, 0.1 W, 0603; Manufacturer: Yageo America; CompType: Resistor; Value: 30.0k; Res_ohm: 30000; Value_Code: 30k0; Tolerance_%: 1; Power_W: 0.1; Value2: 0.1W; VDC_V: 150; TempCo: 200 ppm/C; U/M: EA; AEC Category: Q200
R76 = RC0603FR-0720KL: RES, 20.0 k, 1%, 0.1 W, 0603; Manufacturer: Yageo America; CompType: Resistor; Value: 20.0k; Res_ohm: 20000; Value_Code: 20k0; Tolerance_%: 1; Power_W: 0.1; Value2: 0.1W; VDC_V: 150; TempCo: 200 ppm/C; EIA_Code: E96; U/M: EA; AEC Category: Q200
R77 R90 R91 = RC0201FR-0710KL: RES, 10.0 k, 1%, 0.05 W, 0201; Manufacturer: Yageo America; CompType: Resistor; Value: 10.0k; Res_ohm: 10000; Value_Code: 10k0; Tolerance_%: 1; Power_W: 0.05; Value2: 0.05W; VDC_V: 25; TempCo: 200 ppm/C; EIA_Code: E96; U/M: EA; AEC Category: Q200; AEC Qualified: N; SizeArea_mm2: 0.18; SizeX_mm: 0.6; SizeY_mm: 0.3; SizeZ_mm: 0.26
R78 R79 = RC0603JR-07560RL: RES, 560, 5%, 0.1 W, 0603; Manufacturer: Yageo America; CompType: Resistor; Value: 560; Value_Code: 560R; Tolerance_%: 5; Power_W: 0.1; Value2: 0.1W; VDC_V: 50; TempCo: 100 ppm/C; EIA_Code: E24; U/M: EA; AEC Category: Q200; SizeArea_mm2: 1.28; SizeX_mm: 1.6; SizeY_mm: 0.8; SizeZ_mm: 1
R87 R89 R93 R94 = ERJ-8RQF3R3V: RES, 3.30, 1%, 0.25 W, 1206; Manufacturer: Panasonic; CompType: Resistor; Value: 3.30; Res_ohm: 3.3; Value_Code: 3R30; Tolerance_%: 1; Power_W: 0.25; Value2: 0.25W; TempCo: 200 ppm/C; U/M: EA; SizeArea_mm2: 5.12; SizeX_mm: 3.2; SizeY_mm: 1.6; SizeZ_mm: 1.35; AEC Category: Q200; Green_Lifecycle: Active; Green_REACh: Passed
R99-R102 R165 R166 = ERJ-3GEY0R00V: RES, 0, 5%, 0.1 W, 0603; Manufacturer: Panasonic; CompType: Resistor; Value: 0; Value_Code: 0000; Tolerance_%: 5; Power_W: 0.1; Value2: 0.1W; VDC_V: 50; TempCo: 600 ppm/C; EIA_Code: E24; U/M: EA; AEC Category: Q200; SizeArea_mm2: 1.28; SizeX_mm: 1.6; SizeY_mm: 0.8; SizeZ_mm: 1; Green_Lifecycle: Active; Green_REACh: Passed
TP1-TP4 TP17-TP22 = 5003: Test Point, Miniature, Orange, TH; Manufacturer: Keystone; CompType: Test Point Loop; ContactFinish: Silver; Green_Lifecycle: Active; Green_REACh: Passed
TP7 TP8 TP15 TP16 = 5128: Test Point, Multipurpose, Grey, TH; Manufacturer: Keystone; CompType: Test Point Loop; SymbolCreator: a0412235; ContactFinish: Silver
TP9-TP14 = TP_H0.45P0.75: Testpoint; Manufacturer: Texas Instruments; CompType: Pad
TP23 = 5001: Test Point, Miniature, Black, TH; Manufacturer: Keystone; CompType: Test Point Loop; ContactFinish: Silver; Green_Lifecycle: Active; Green_REACh: Passed
U8 = CMP-0075392-3: 175-W Stereo, 350-W Mono Ultra-HD Digital-Input Class-D Amplifier with Advanced DSP Processing, DKQ0056A (SSOP-56); Alternate Manufacturer: Texas Instruments; SizeX_mm: 10.35; CompType: IC; SizeAreaWB_mm2: 252.0635; SizeZ_mm: 2.79; SizeY_mm: 18.41; SizeArea_mm2: 190.5435; AEC Category: Q200; AEC Qualified: N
